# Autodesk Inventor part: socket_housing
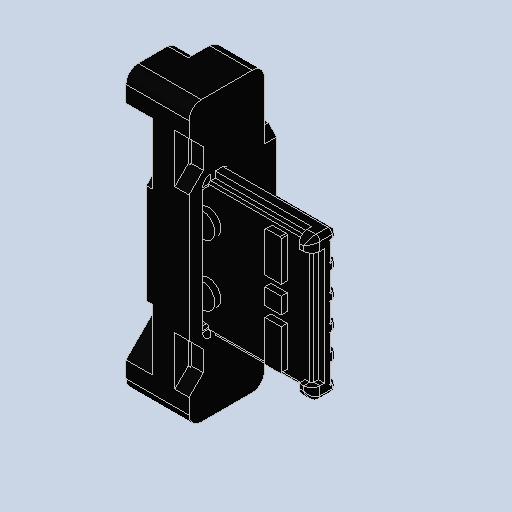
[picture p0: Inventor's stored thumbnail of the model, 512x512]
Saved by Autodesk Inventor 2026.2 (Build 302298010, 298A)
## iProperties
Created: 2026-10
Part Number: socket_housing
Material: Générique
Document SubType Name: Modeling
Designer: mel
Density: 1 g/cm^3
Appearance: Par défaut
Author: mel
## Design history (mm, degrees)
feature "Base1"
node "Solide1"
